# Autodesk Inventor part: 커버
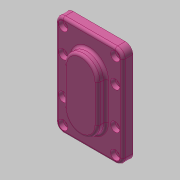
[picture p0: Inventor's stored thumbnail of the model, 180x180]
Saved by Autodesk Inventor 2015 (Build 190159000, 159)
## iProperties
Created: 2019-03
Part Number: 커버
Material: 알루미늄 6061
Document SubType Name: Modeling
Designer: mduedu
Density: 1 g/cm^3
Appearance: 분홍색
Author: mduedu
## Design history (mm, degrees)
sketch "스케치1"
  geometry: L1 (-60, 40)-(60, 40); L2 (60, 40)-(60, -40); L3 (60, -40)-(-60, -40); L4 (-60, -40)-(-60, 40); L5 (-60, 40)-(60, -40); L6 (60, 40)-(-60, -40); 1 further point
  constraints: 12 end point, 2 midpoint, 2 parallel, 1 horizontal, 1 perpendicular
  dimensions: "d59" = 120 distance of L2.end L3.end; "d60" = 80 distance of L1.end L2.end
extrude "돌출1" new body sketch "스케치1" distance "d4" = 12; taper "d5" = 0 deg
sketch "스케치2"
  geometry: L1 (-20, -22)-(20, -22); L2 (20, -22)-(20, 22); L3 (20, 22)-(-20, 22); L4 (-20, 22)-(-20, -22); L5 (-20, -22)-(20, 22); L6 (20, -22)-(-20, 22); 3 further points
  constraints: 12 end point, 4 midpoint, 2 horizontal alignment, 2 parallel, 1 horizontal, 1 perpendicular, 4 other
  dimensions: "d6" = 40 distance between parallel lines of L2 L4; "d8" = 44 distance between parallel lines of L1 L3
extrude "돌출2" join sketch "스케치2" distance "d9" = 10; taper "d10" = 0 deg
fillet "모깎기1" dims "d11" = 9
fillet "모깎기2" dims "d12" = 3
sketch "스케치3"
  geometry: L1 (-31, -60)-(31, -60) reference; L2 (-40, 51)-(-40, -51) reference; L3 (31, 60)-(-31, 60) reference; L4 (40, -51)-(40, 51) reference; L5 (-17, -22)-(-17, 22) reference; L6 (17, 22)-(17, -22) reference; L7 (-31, 51)-(31, 51); L8 (31, 51)-(31, -51); L9 (31, -51)-(-31, -51); L10 (-31, -51)-(-31, 51); A1 r 9 centre (31, -51) between (31, -60) and (40, -51) reference; A2 r 9 centre (-31, -51) between (-40, -51) and (-31, -60) reference; A3 r 9 centre (-31, 51) between (-31, 60) and (-40, 51) reference; A4 r 9 centre (31, 51) between (40, 51) and (31, 60) reference; A5 r 17 centre (0, -22) between (-17, -22) and (17, -22) reference; A6 r 17 centre (0, 22) between (17, 22) and (-17, 22) reference; 9 further points
  constraints: 8 end point, 4 coincident, 4 horizontal alignment, 4 point on line, 2 parallel, 1 horizontal, 1 perpendicular
hole "구멍2" sketch "스케치3" at (-31, 51), (31, 51), (31, -51), (-31, -51), (-31, 22), (-31, -22), (31, 22), (31, -22) diameter "d28" = 5.5; stored, may be unused: countersink angle "d32" = 90 deg, drill point angle "d34" = 118 deg; dims "d29" = 6, "d30" = 4, "d31" = 2, "d33" = 8
sketch "스케치9"
  geometry: L1 (40, -51)-(40, 51) reference; L2 (31, 60)-(-31, 60) reference; L3 (-40, 51)-(-40, -51) reference; L4 (-31, -60)-(31, -60) reference; L5 (23, -22)-(23, 22) reference; L6 (-23, 22)-(-23, -22) reference; C1 r 2.75 at (31, 22) reference; C2 r 2.75 at (-31, 22) reference; C3 r 2.75 at (31, -51) reference; C4 r 2.75 at (-31, 51) reference; C5 r 2.75 at (31, 51) reference; C6 r 2.75 at (-31, -51) reference; C7 r 2.75 at (-31, -22) reference; C8 r 2.75 at (31, -22) reference; A1 r 9 centre (31, -51) between (31, -60) and (40, -51) reference; A2 r 9 centre (31, 51) between (40, 51) and (31, 60) reference; A3 r 9 centre (-31, 51) between (-31, 60) and (-40, 51) reference; A4 r 9 centre (-31, -51) between (-40, -51) and (-31, -60) reference; A5 r 23 centre (0, -22) between (-23, -22) and (23, -22) reference; A6 r 23 centre (0, 22) between (23, 22) and (-23, 22) reference; 9 further points
  constraints: 8 coincident
hole "구멍4" sketch "스케치9" at (-31, 51), (31, 51), (31, 22), (-31, 22), (-31, -22), (31, -22), (31, -51), (-31, -51) diameter "d69" = 11; stored, may be unused: countersink angle "d73" = 90 deg, drill point angle "d75" = 0 deg; dims "d70" = 6, "d71" = 4, "d72" = 2, "d74" = 5.4
fillet "모깎기3" dims "d68" = 3
sketch "스케치6"
  geometry: C1 r 12.5 at (0, 22); 1 further point
  constraints: 1 centre point, 1 vertical alignment
  dimensions: "d43" = 25 diameter of C1; "d45" = 22 distance of C1.centre point (0, 0)
extrude "돌출5" cut sketch "스케치6" distance "d47" = 15; taper "d48" = 0 deg
node "솔리드1"
mirror "대칭1"
node "투영된 루프2"
node "투영된 루프3"
node "투영된 루프4"
